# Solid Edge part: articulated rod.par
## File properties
Author: Vicky Raina
Template: Normal.par
Last saved by: Robert a Rhodes jr
Revision: 7
Application: Solid Edge
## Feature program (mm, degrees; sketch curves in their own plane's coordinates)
sketch for "unnamed Protrusion 1" plane through (0, 0, 0) normal (0, -1, 0) x-axis (1, 0, 0)
  line (-89, 9) -> (-89, -9)
  line (-89, -9) -> (89, -9)
  line (89, -9) -> (89, 9)
  line (89, 9) -> (-89, 9)
extrude "unnamed Protrusion 1" add finite 18 symmetric
sketch for "unnamed Protrusion 2" plane through (0, 0, 0) normal (0, 0, 1) x-axis (1, 0, 0)
  circle centre (89, 0) radius 17.5
extrude "unnamed Protrusion 2" add finite 42 symmetric
sketch for "unnamed Hole 1" plane through (89, 0, 21) normal (0, 0, 1) x-axis (1, 0, 0)
  hole centre (0, 0) bore radius 12
hole "unnamed Hole 1" through
sketch for "unnamed Protrusion 3" plane through (0, 0, 0) normal (0, 0, 1) x-axis (1, 0, 0)
  circle centre (-89, 0) radius 12
extrude "unnamed Protrusion 3" add finite 28 symmetric
sketch for "unnamed Hole 2" plane through (-89, 0, 14) normal (0, 0, 1) x-axis (1, 0, 0)
  hole centre (0, 0) bore radius 7.5
hole "unnamed Hole 2" through
fillet "unnamed Round 1"
sketch for "unnamed Cutout 1" plane through (-2.9078, 0, 9) normal (0, 0, 1) x-axis (1, 0, 0)
  line (-64.0922, 6.35) -> (65.9078, 6.35)
  arc centre (-64.0922, 0) radius 6.35 from (-64.0922, -6.35) to (-64.0922, 6.35) cw
  line (-64.0922, -6.35) -> (65.9078, -6.35)
  arc centre (65.9078, 0) radius 6.35 from (65.9078, 6.35) to (65.9078, -6.35) cw
  dimension (linear) = 64.0922
extrude "unnamed Cutout 1" cut finite 6.5 along -normal
mirror "unnamed Mirror 1" of "unnamed Cutout 1"
pattern "unnamed Pattern 1"
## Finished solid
Body 1: solid body, 26 faces, 56 edges, 32 vertices.
  Faces by surface: plane 14, cylinder 12
  Edges by curve: circle 28, line 28
Bounding box of the edges (mm): 207.500 x 35.000 x 42.000, from (-101, -17.5, -21) to (106.5, 17.5, 21).
Cylindrical faces by radius (mm): R6.35 x4, R7.5 x1, R12 x2, R17.5 x1, R24 x4
Planar faces by outward normal: +y 3, +z 4, -y 3, -z 4
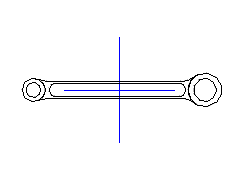
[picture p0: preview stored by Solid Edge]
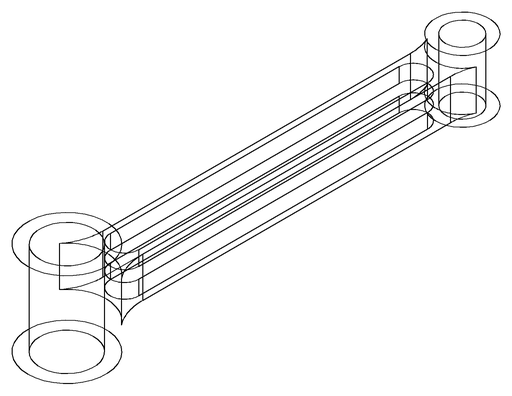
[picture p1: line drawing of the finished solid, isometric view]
